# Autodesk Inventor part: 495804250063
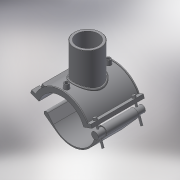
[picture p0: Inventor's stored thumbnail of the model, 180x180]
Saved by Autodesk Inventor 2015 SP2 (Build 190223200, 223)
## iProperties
Created: 2017-07
Part Number: 495804250063
Material: Generic
Description: PLASSON BRANCH SADDLE 250-63
Document SubType Name: Modeling
Designer: KIM
Density: 1 g/cm^3
Appearance: Default
Author: KIM
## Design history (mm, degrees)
derived "495804.ipt"
feature "Solid1::495804.ipt"
feature "Solid2::495804.ipt"
tag "TaggingFeature1"
body "Solid1"
body "Solid2"
other parameters: "d2" = 327.6, "d3" = 62.5, "d4" = 176, "d5" = 0, "d6" = 0.1, "d8" = 0, "d19" = 6, "d20" = 6, "d21" = 105.6, "d23" = 0, "d24" = 52.8, "d26" = 0, "d27" = 3, "d28" = 3, "d29" = 3, "d30" = 83.33333, "d31" = 6, "d32" = 0, "d33" = 0, "d34" = 0.6, "d40" = 147.68, "d41" = 69.3, "d43" = 0, "d45" = 0, "d47" = 244, "d48" = 63, "d50" = 0, "d70" = 15, "d72" = 0, "d73" = 6, "d75" = 5, "d76" = 0, "d77" = 12.5, "d78" = 155, "d79" = 15, "d80" = 70.4, "d82" = 5 deg, "d84" = 4, "d85" = 14, "d86" = 0, "d87" = 3, "d88" = 0, "d89" = 1, "d90" = 1, "d91" = 140.8, "d92" = 0, "d93" = 0.5, "d94" = 131.57895, "d96" = 289.68, "d97" = 3.52, "d98" = 0, "d102" = 1.89, "d103" = 50.4, "d105" = 0, "d109" = -34, "d117" = 0.63, "d120" = 140 deg, "d121" = 24.228, "d122" = 20 deg, "d123" = 568, "d124" = 170.4, "d126" = 0, "d143" = 262.5, "d150" = 45, "d159" = 6.8, "d161" = 6.25, "d162" = 105.6, "d163" = 0, "d168" = 129.09091, "d173" = 1, "d175" = 125, "d176" = 20 deg, "d177" = 17.5, "d178" = 34, "d180" = 0, "d185" = 57.2, "d186" = 57.2, "d187" = 142, "d188" = 10.2, "d189" = 17.5, "d190" = 0, "d191" = 213, "d200" = 17, "d202" = 0, "d216" = 158.4, "d217" = 0, "d221" = 65.12, "d222" = 17.5, "d223" = 10.5, "d224" = 125, "d225" = 10.5, "d227" = 36, "d230" = 152.5, "d236" = 20 deg, "d237" = 149, "d238" = 20 deg, "d239" = 17.5, "B_" = 252, "H_" = 102, "L_" = 176, "d_t" = 6, "d_1" = 63, "H_1" = 85, "d1" = 284, "d148" = 6.25, "d160" = 6.25
